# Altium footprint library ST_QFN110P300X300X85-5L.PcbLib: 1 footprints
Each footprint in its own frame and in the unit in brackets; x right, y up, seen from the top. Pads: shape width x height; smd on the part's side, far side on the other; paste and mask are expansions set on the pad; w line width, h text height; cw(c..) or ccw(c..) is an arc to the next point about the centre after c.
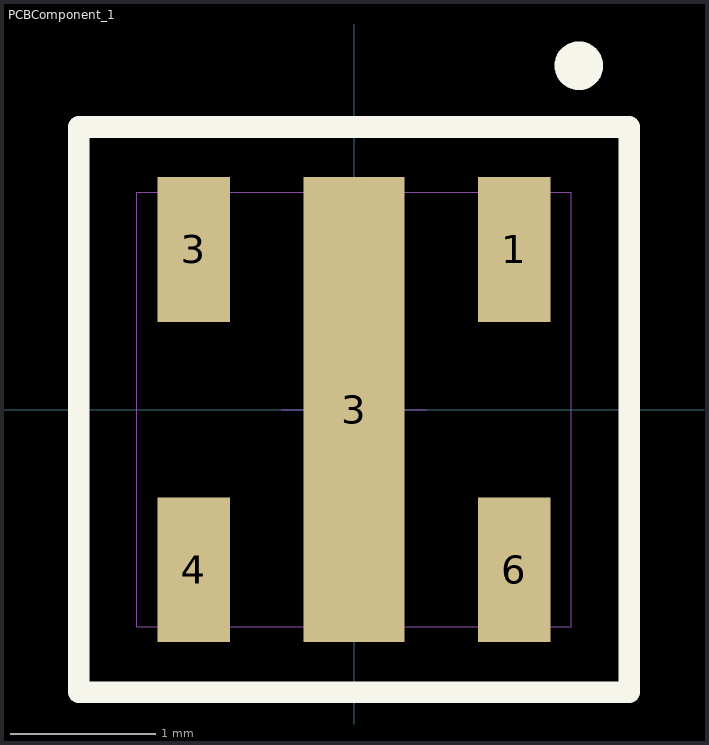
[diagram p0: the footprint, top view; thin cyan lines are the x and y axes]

## PCBComponent_1 [mm]
pads (5):
  rect 0.5x1 smd paste-20 mask+0.025: 1(1.105,1.105) 3(-1.105,1.105) 4(-1.105,-1.105) 6(1.105,-1.105)
  rect 0.7x3.21 smd paste-20 mask+0.025: 3(0,0)
Top Overlay:
  circle w0.2: c1.551,2.373 r0.068
  lines w0.15: -1.9,-1.95 -1.9,1.95 1.9,1.95 1.9,-1.95 -1.9,-1.95
Top Paste:
  rectangle: -0.332,-1.523 0.332,1.523
  rectangle: 0.868,-1.58 1.342,-0.63
  rectangle: -1.342,-1.58 -0.868,-0.63
  rectangle: -1.342,0.63 -0.868,1.58
  rectangle: 0.868,0.63 1.342,1.581
Mechanical 15:
  lines w0: -1.5,-1.5 -1.5,1.5 1.5,1.5 1.5,-1.5 -1.5,-1.5
  lines w0.001: -0.5,0 0.5,0 ; 0,-0.5 0,0.5
3D body: height 0.85, standoff 0.02, extent -1.5,-1.5 1.5,1.5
